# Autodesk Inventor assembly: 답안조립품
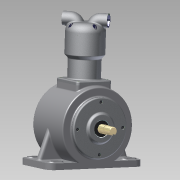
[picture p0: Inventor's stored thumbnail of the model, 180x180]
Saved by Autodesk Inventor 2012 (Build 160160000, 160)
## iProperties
Created: 2015-06
Part Number: 답안조립품
Document SubType Name: Assembly
Designer: User
Author: User
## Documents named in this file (15)
- C:\Documents and Settings\User\바탕 화면\450605V1015\답안조립품.iam
- C:\Documents and Settings\User\바탕 화면\450605V1015\본체.ipt
- C:\Documents and Settings\User\바탕 화면\450605V1015\메인 크랭크 축-구동부.ipt
- C:\Documents and Settings\User\바탕 화면\450605V1015\메인커버.ipt
- C:\Documents and Settings\User\바탕 화면\450605V1015\베어링 6204.ipt
- C:\Documents and Settings\User\바탕 화면\450605V1015\베어링 NA 4902.ipt
- C:\Documents and Settings\User\바탕 화면\450605V1015\실린더.ipt
- C:\Documents and Settings\User\바탕 화면\450605V1015\실린더헤드.ipt
- C:\Documents and Settings\User\바탕 화면\450605V1015\오일실.ipt
- C:\Documents and Settings\User\바탕 화면\450605V1015\커넥팅 로드.ipt
- C:\Documents and Settings\User\바탕 화면\450605V1015\크랭크 서브축.ipt
- C:\Documents and Settings\User\바탕 화면\450605V1015\피스톤.ipt
- C:\Documents and Settings\User\바탕 화면\450605V1015\피스톤 핀.ipt
- C:\Documents and Settings\User\바탕 화면\450605V1015\M4x0.7.ipt
- C:\Documents and Settings\User\바탕 화면\450605V1015\M5x0.8.ipt
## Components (14 placed, 4 different names)
1. 피스톤:1
2. 피스톤 핀:1
3. M4x0.7:2 — 각도:2, 각도:3, 각도:6
4. M4x0.7:3 — 각도:3
5. M4x0.7:4 — 각도:4, 각도:5, 각도:6
6. M4x0.7:5 — 각도:4, 각도:5
7. M5x0.8:1 — 각도:1
8. M5x0.8:2
9. M5x0.8:3
10. M5x0.8:4
11. M4x0.7:1 — 각도:7
12. M4x0.7:6
13. M4x0.7:7
14. M4x0.7:8
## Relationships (7: Angle 7)
- 각도:1 [Angle]: M5x0.8:1
- 각도:2 [Angle]: M4x0.7:2
- 각도:3 [Angle]: M4x0.7:2 ↔ M4x0.7:3
- 각도:4 [Angle]: M4x0.7:4 ↔ M4x0.7:5
- 각도:5 [Angle]: M4x0.7:4 ↔ M4x0.7:5
- 각도:6 [Angle]: M4x0.7:2 ↔ M4x0.7:4
- 각도:7 [Angle]: M4x0.7:1
